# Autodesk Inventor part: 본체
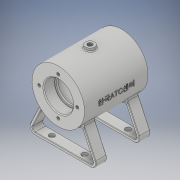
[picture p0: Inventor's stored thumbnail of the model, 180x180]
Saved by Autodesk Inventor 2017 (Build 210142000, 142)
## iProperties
Part Number: 본체
Material: 일반
Document SubType Name: Modeling
Designer: Administrator
Density: 1 g/cm^3
Appearance: 기본값
Author: Administrator
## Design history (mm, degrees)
sketch "스케치3"
  geometry: L1 (16, 0)-(16, -12); L2 (16, -12)-(14, -12); L3 (14, -12)-(14, -14); L4 (14, -14)-(21, -14); L5 (21, -14)-(21, -56); L6 (21, -56)-(14, -56); L7 (14, -56)-(14, -58); L8 (14, -58)-(16, -58); L9 (16, -58)-(16, -70); L10 (16, -70)-(29, -70); L11 (29, -70)-(29, 0); L12 (29, 0)-(16, 0); L13 (0, 0)-(0, -70)
  constraints: 26 end point, 10 perpendicular, 2 point on line, 2 vertical, 1 horizontal
  dimensions: "d0" = 70 distance of L13.start L13.end; "d1" = 12 distance of L1.start L1.end; "d2" = 2 distance of L2.end L3.end; "d3" = 42 distance of L4.end L5.end; "d4" = 12 distance of L8.end L9.end; "d5" = 32 diameter of L9 L13; "d6" = 58 diameter of L11 L13; "d7" = 28 diameter of L7 L13; "d8" = 42 diameter of L5 L13; "d9" = 28 diameter of L3 L13; "d10" = 32 diameter of L1 L13
revolve "회전1" sketch "스케치3" stored, may be unused: angle "d11" = 90 deg
sketch "스케치4"
  geometry: C1 r 16 at (0, 0) reference; C2 r 29 at (0, 0) reference; A1 r 21 centre (0, 0) between (0, 21) and (21, 0); 3 further points
  constraints: 4 point on circle, 2 horizontal alignment, 2 vertical alignment, 1 centre point, 1 coincident
  dimensions: "d12" = 42 diameter of A1
hole "구멍1" sketch "스케치4" at (0, 21), (21, 0), (-21, 0), (0, -21) diameter "d13" = 3.242; stored, may be unused: countersink angle "d17" = 90 deg, drill point angle "d19" = 118 deg; dims "d14" = 8, "d15" = 4, "d16" = 2, "d18" = 10
node "작업 평면1"
node "작업 평면2"
sketch "스케치5"
  geometry: L1 (-29, 0)-(29, 0) reference; C1 r 5 at (0, -35); 1 further point
  constraints: 1 centre point, 1 vertical alignment
  dimensions: "d21" = 10 diameter of C1; "d22" = 35 distance from line of L1 C1.centre
extrude "돌출1" join sketch "스케치5" stored distance "d23" = 10; taper "d24" = 0 deg
hole "구멍2" diameter "d27" = 5.188; stored, may be unused: countersink angle "d31" = 90 deg, drill point angle "d33" = 0 deg; dims "d28" = 6, "d29" = 4, "d30" = 2, "d32" = 8, "d34" = 10, "d35" = 10
hole "구멍3" diameter "d38" = 3; stored, may be unused: countersink angle "d42" = 90 deg, drill point angle "d44" = 118 deg; dims "d36" = 10, "d37" = 10, "d39" = 6, "d40" = 4, "d41" = 2, "d43" = 15
chamfer "모따기1" distance "d45" = 1; stored, may be unused: second distance "d46" = 2, angle "d47" = 45 deg
node "작업 평면3"
sketch "스케치6"
  geometry: L1 (0, 0)-(-10.945, -30.07); L2 (0, 0)-(32, 0)
  constraints: 4 end point, 1 equal length, 1 horizontal
  dimensions: "d49" = 32 distance of L1.start L1.end; "d50" = 110 deg angle of L1 L2
node "작업 평면4"
sketch "스케치7"
  geometry: C1 r 6 at (0, 0); 4 further points
  constraints: 1 centre point, 1 coincident
  dimensions: "d51" = 12 diameter of C1
extrude "돌출2" join sketch "스케치7" stored distance "d52" = 10; taper "d53" = 0 deg
hole "구멍4" diameter "d56" = 5.188; stored, may be unused: countersink angle "d60" = 90 deg, drill point angle "d62" = 118 deg; dims "d54" = 10, "d55" = 10, "d57" = 12, "d58" = 4, "d59" = 2, "d61" = 16
node "작업 평면5"
sketch "스케치8"
  geometry: L1 (-22.743, -17.993)-(-36.02, -46.464); L2 (-30.582, -55)-(30.582, -55); L3 (36.02, -46.464)-(22.743, -17.993); L4 (20.574, -20.438)-(33.301, -47.732); L5 (30.582, -52)-(-30.582, -52); L6 (-33.301, -47.732)-(-20.574, -20.438); C1 r 1.621 at (-21, 0) reference; C2 r 1.621 at (0, 21) reference; C3 r 1.621 at (21, 0) reference; C4 r 1.621 at (0, -21) reference; C5 r 16 at (0, 0) reference; A1 r 29 centre (0, 0) between (22.743, -17.993) and (-22.743, -17.993) reference; A2 r 6 centre (-30.582, -49) between (-36.02, -46.464) and (-30.582, -55); A3 r 6 centre (30.582, -49) between (30.582, -55) and (36.02, -46.464); A4 r 3 centre (30.582, -49) between (30.582, -52) and (33.301, -47.732); A5 r 3 centre (-30.582, -49) between (-33.301, -47.732) and (-30.582, -52); 4 further points
  constraints: 12 end point, 12 point on circle, 4 centre point, 4 point on line, 4 tangent, 1 horizontal, 1 midpoint, 1 vertical alignment, 2 other
  dimensions: "d64" = 80 distance of point (-40, -55) point (40, -55); "d66" = 65 deg angle of L2 L1; "d67" = 6 radius of A3 (derived); "d68" = 65 deg angle of L2 L3; "d69" = 55 distance from line of point (0, 0) L2; "d70" = 6 radius of A2; "d71" = 3 distance between parallel lines of L3 L4; "d72" = 3 distance between parallel lines of L1 L6; "d73" = 3 distance between parallel lines of L2 L5
extrude "돌출3" join sketch "스케치8" distance "d74" = 12; taper "d75" = 0 deg
sketch "스케치9"
  geometry: L1 (0, 0)-(61.164, 0) reference; 5 further points
  constraints: 2 horizontal alignment, 2 vertical alignment
  dimensions: "d76" = 18 horizontal distance of point (12.582, 6) point (30.582, -5); "d77" = 6 distance from line of L1 point (12.582, 6); "d78" = 36 distance of point (12.582, 6) point (48.582, 6); "d79" = 48 distance of point (12.582, 54) point (12.582, 6)
hole "구멍5" sketch "스케치9" at (12.582, 6), (12.582, 54), (48.582, 54), (48.582, 6) diameter "d80" = 6; stored, may be unused: countersink angle "d84" = 90 deg, drill point angle "d86" = 118 deg; dims "d81" = 12, "d82" = 4, "d83" = 2, "d85" = 16
fillet "모깎기1" dims "d87" = 0.5
fillet "모깎기2" dims "d88" = 3
fillet "모깎기3" dims "d89" = 1
fillet "모깎기4" dims "d90" = 0.3
chamfer "모따기2" distance "d91" = 1; stored, may be unused: second distance "d92" = 2, angle "d93" = 45 deg
node "작업 평면6"
sketch "스케치10"
  geometry: L1 (29, 0)-(29, -70) reference; 2 further points
  constraints: 1 other
  dimensions: "d95" = 35 distance of point (0, -35) point (0, 0); "d96" = 29 distance from line of L1 point (0, -35)
feature "엠보싱1" sketch "스케치10" dims "d97" = 0.5, "d98" = 0
fillet "모깎기5" dims "d99" = 3
node "솔리드1"
mirror "미러1"
mirror "미러2"
node "투영된 루프1"
node "투영된 루프2"
other parameters: "d20" = 32, "d48" = -35, "d63" = -5, "d94" = 39.5
